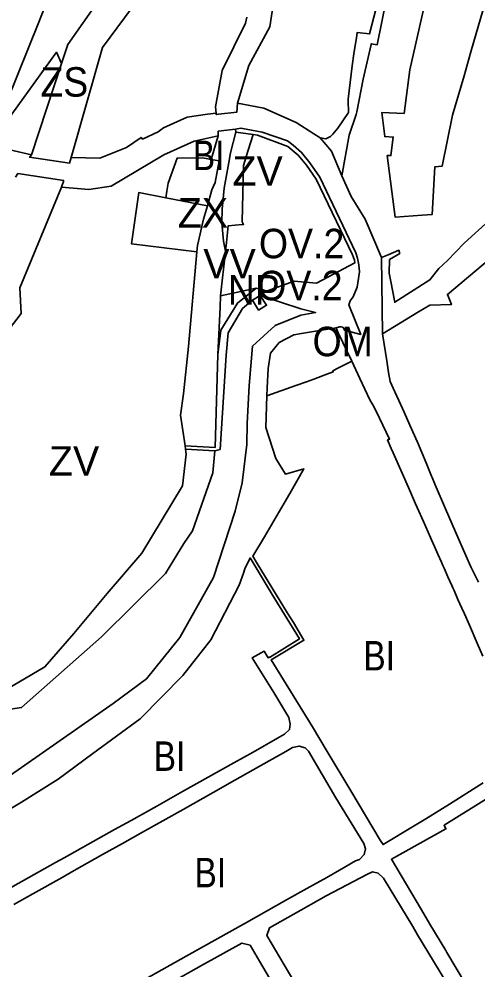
# Model space of a CAD drawing. Extents: x -650451 to -642268, y -1075216 to -1066610.
# Drawn here: x -646146.5 to -645913, y -1070420.9 to -1069937.3 of the extents above; entities that cross this region are included whole.
import ezdxf

# ---------------------------------------------------------------- set-up
doc = ezdxf.new("R2010")
doc.units = 0
doc.header["$LTSCALE"] = 6
doc.layers.add('1', color=7, linetype='Continuous', lineweight=35)
doc.layers.add('2', color=7, linetype='Continuous')

msp = doc.modelspace()

# ---------------------------------------------------------------- linework, layer by layer
at = {"layer": '1'}
for p, q in [((-646124.96, -1069959.99), (-646140.27, -1070006.41)), ((-646036.36, -1069993.34), (-646036.22, -1069994.85)), ((-646027.457, -1069996.063), (-646036.22, -1069994.85)), ((-646045.22, -1069996.81), (-646048.71, -1070008.77)), ((-646140.27, -1070006.41), (-646161.71, -1070001.55)), ((-646120.91, -1070010.7), (-646119.95, -1070007.73)), ((-646123.74, -1070019.41), (-646124.87, -1070022.9)), ((-646050.67, -1070032.37), (-646071.84, -1070028.3)), ((-646041.54, -1070055.39), (-646043.98, -1070078.24)), ((-645961.65, -1070097.54), (-645962.08, -1070058.72)), ((-646043.98, -1070078.24), (-646025.87, -1070074.25)), ((-646027.71, -1070080.48), (-646023.84, -1070078.03)), ((-646061.8, -1070156.29), (-646062.06, -1070154.56)), ((-646061.8, -1070156.29), (-646046.84, -1070157.03))]:
    msp.add_line(p, q, dxfattribs=at)
for points in [[(-645957.35, -1069496.35), (-645944.19, -1069571.66), (-645941.5, -1069609.76), (-645942.58, -1069624.73), (-645943.44, -1069636.76), (-645948.61, -1069657.43), (-645970.08, -1069692.61), (-646009.2, -1069734.98), (-646031.15, -1069747.2), (-646040.53, -1069755.58), (-646051.95, -1069771.98), (-646062.91, -1069794.85), (-646068.64, -1069840.94), (-646076.24, -1069876.52), (-646086.68, -1069900.4), (-646121.75, -1069950.24), (-646124.96, -1069959.99)], [(-645929.263, -1069881.347), (-645947.741, -1069963.127), (-645950.559, -1069985.34), (-645962, -1069984.94), (-645960.43, -1069997.16), (-645956.11, -1069997.41), (-645957.26, -1070006.85), (-645959.2, -1070006.76), (-645955.17, -1070038.09), (-645941.45, -1070037.17), (-645936.31, -1070036.82), (-645934.98, -1070012.58), (-645931.29, -1070012.23), (-645925.98, -1069986.2), (-645920.018, -1069966.193), (-645916.63, -1069954.05), (-645907.94, -1069924.17)], [(-646077.78, -1069916.11), (-646104.04, -1069951.75), (-646119.95, -1070007.73)], [(-646035.42, -1069980.12), (-646029.65, -1069960.92), (-646018.88, -1069941.32), (-646015.46, -1069918.63)], [(-646136.88, -1069923.39), (-646136.23, -1069923.94), (-646131.96, -1069927.57), (-646135.28, -1069935.88), (-646136.46, -1069938.84), (-646152.59, -1069978.9), (-646160.09, -1069997.51)], [(-645993.26, -1069997.71), (-645990.38, -1069998.22), (-645988.11, -1069997.06), (-645986.87, -1069995.99), (-645984.31, -1069992.78), (-645978.91, -1069984.88), (-645979.02, -1069978.79), (-645979.11, -1069978.07), (-645977.08, -1069961.2), (-645976.18, -1069954.95), (-645974.7, -1069945.76), (-645974.41, -1069944.11), (-645968.18, -1069944.85), (-645963.78, -1069927.8)], [(-645982.2, -1070017.17), (-645978.48, -1069996.42), (-645975, -1069985.96), (-645974.71, -1069984.49), (-645971.46, -1069967.93), (-645967.35, -1069950.26), (-645967.3, -1069949.88), (-645964.26, -1069950.41), (-645959.68, -1069927.82)], [(-646046.28, -1069985.18), (-646046.63, -1069982.04), (-646043.2, -1069963.46), (-646031.24, -1069939.45), (-646030.62, -1069936.3)], [(-645962.08, -1070058.72), (-645958.65, -1070057.27), (-645953.31, -1070055.02), (-645952.77, -1070056.63), (-645958.05, -1070059.79), (-645958.13, -1070066.59), (-645957.02, -1070072.53), (-645956.65, -1070074.52), (-645955.34, -1070081.48), (-645937.48, -1070070.14), (-645932.87, -1070064.33), (-645928.56, -1070060.21), (-645920.07, -1070051.36), (-645907.27, -1070039.82), (-645904.28, -1070034.66), (-645902.17, -1070025.11), (-645907.7, -1069998.79), (-645907.79, -1069986.84), (-645905.05, -1069967.45), (-645901.65, -1069959.39), (-645887.58, -1069932.97)], [(-646161.71, -1070001.55), (-646127.44, -1069954.2), (-646124.96, -1069959.99)], [(-646046.28, -1069985.18), (-646046.2, -1069985.92), (-646045.07, -1069985.73), (-646035.75, -1069984.73), (-646035.42, -1069980.12)], [(-645993.26, -1069997.71), (-645996.47, -1069995.79), (-646005.51, -1069989.96), (-646021.98, -1069982.59), (-646035.42, -1069980.12)], [(-646119.95, -1070007.73), (-646105.35, -1070008.18), (-646091.87, -1070002.66), (-646084.39, -1069997.53), (-646083.67, -1069998.4), (-646075.69, -1069994.68), (-646073.1, -1069992.61), (-646060.94, -1069987.19), (-646050.68, -1069985.78), (-646046.28, -1069985.18)], [(-646045.22, -1069996.81), (-646045.27, -1069994.44), (-646036.36, -1069993.34)], [(-646036.22, -1069994.85), (-646038.93, -1070005.37), (-646039.83, -1070010.38), (-646042.16, -1070023.43), (-646043.21, -1070034.06), (-646043.4, -1070040.96), (-646042.55, -1070050.3), (-646041.54, -1070055.39)], [(-645985.08, -1070094.46), (-645983.46, -1070094.05), (-645982.59, -1070093.99), (-645981.81, -1070094.21), (-645981.22, -1070094.8), (-645980.87, -1070095.64), (-645972.61, -1070097.85), (-645978.63, -1070082.76), (-645977.95, -1070080.77), (-645976.51, -1070078.72), (-645974.45, -1070073.8), (-645974.15, -1070071.55), (-645973.35, -1070065.91), (-645973.7, -1070062.5), (-645974.34, -1070059.01), (-645975.23, -1070056.35), (-645993.49, -1070017.76), (-645998.52, -1070010.49), (-646002.77, -1070005.2), (-646006.96, -1070001.52), (-646009.87, -1069999.35), (-646022.89, -1069994.84), (-646033.61, -1069992.78), (-646036.36, -1069993.34)], [(-646124.87, -1070022.9), (-646111.08, -1070024.01), (-646099.71, -1070022.3), (-646072.89, -1070006.37), (-646057.37, -1069999.5), (-646045.22, -1069996.81)], [(-646041.54, -1070055.39), (-646041.01, -1070051.13), (-646040.1, -1070042.52), (-646032.95, -1070041.88), (-646032.292, -1070041.824), (-646032.994, -1070040.508), (-646032.35, -1070011.78), (-646030.01, -1070004.12), (-646027.457, -1069996.063)], [(-646027.457, -1069996.063), (-646025.17, -1069996.38), (-646009.73, -1070002.19), (-646004.53, -1070006.52), (-646000.31, -1070011.7), (-645995.37, -1070018.86), (-645976.76, -1070057.39), (-645975.86, -1070060.04), (-645975.667, -1070061.487), (-645995.242, -1070071.816), (-646006.589, -1070070.734), (-646020.53, -1070075.79), (-646022.31, -1070075.07), (-646025.87, -1070074.25)], [(-645982.2, -1070017.17), (-645987.45, -1070004.6), (-645993.26, -1069997.71)], [(-646140.27, -1070006.41), (-646141.14, -1070007.63), (-646120.91, -1070010.7)], [(-646048.71, -1070008.77), (-646051.35, -1070008.32), (-646053.4, -1070007.98), (-646066.06, -1070008.11), (-646070.67, -1070020.78), (-646071.32, -1070024.95), (-646071.84, -1070028.3)], [(-646050.67, -1070032.37), (-646048.34, -1070024.27), (-646046.8, -1070020.55), (-646044.63, -1070009.47), (-646048.71, -1070008.77)], [(-646123.74, -1070019.41), (-646147.11, -1070016.01), (-646148.34, -1070017.73)], [(-645982.2, -1070017.17), (-645977.5, -1070027.72), (-645970.39, -1070039.12), (-645962.08, -1070058.72)], [(-646160.94, -1070129.14), (-646160.6, -1070127.76), (-646151.53, -1070095.19), (-646145.47, -1070087.27), (-646146.19, -1070074.15), (-646124.87, -1070022.9)], [(-646071.84, -1070028.3), (-646085.64, -1070025.65), (-646089.25, -1070051.8), (-646056.09, -1070055.76)], [(-646056.09, -1070055.76), (-646055.78, -1070052.52), (-646052.63, -1070039.21), (-646050.67, -1070032.37)], [(-646056.09, -1070055.76), (-646060.36, -1070103.99), (-646062.8, -1070128.04), (-646064.44, -1070138.99), (-646062.06, -1070154.56)], [(-645901.22, -1070066.97), (-645907.18, -1070059.55), (-645928.51, -1070077.51), (-645926.55, -1070082.68), (-645937.53, -1070082.92), (-645943.32, -1070086.36), (-645961.65, -1070097.54)], [(-646025.87, -1070074.25), (-646035.35, -1070081.89), (-646043.88, -1070095.63), (-646045.35, -1070108.04)], [(-646023.84, -1070078.03), (-646003.18, -1070084.88), (-645995.59, -1070086.74), (-646003.08, -1070088.07), (-646016.12, -1070093.28), (-646027.66, -1070103.79), (-646029.45, -1070123.88), (-646030.51, -1070143.17), (-646030.66, -1070153.86), (-646033.06, -1070173.32), (-646036.61, -1070187.84), (-646047.55, -1070221.59), (-646064.78, -1070252.22), (-646081.74, -1070273.1), (-646098.57, -1070285.71), (-646152.57, -1070323.39), (-646159.26, -1070328.75)], [(-646046.84, -1070157.03), (-646044.21, -1070156.41), (-646041.14, -1070108.39), (-646040.05, -1070097.06), (-646032.79, -1070084.73), (-646027.71, -1070080.48)], [(-646043.98, -1070078.24), (-646044.25, -1070084.03), (-646045.35, -1070108.04)], [(-646023.84, -1070078.03), (-646020.6, -1070082.99), (-646024.66, -1070085.49), (-646027.71, -1070080.48)], [(-646020.39, -1070129.18), (-646020.23, -1070125.05), (-646019.71, -1070115.15), (-646018.64, -1070107.32), (-646014.13, -1070101.92), (-646006.74, -1070098.07), (-646002.8, -1070097.37), (-645992.6, -1070095.69), (-645985.08, -1070094.46)], [(-645985.08, -1070094.46), (-645984.1, -1070097.01), (-645977.22, -1070111.51)], [(-645961.65, -1070097.54), (-645959.4, -1070111.28), (-645958.45, -1070117.18), (-645957.7, -1070121.77), (-645955.23, -1070127.14), (-645955.07, -1070127.5), (-645950.6, -1070137.43), (-645947.63, -1070144.02), (-645943.7, -1070152.62), (-645939.36, -1070163.29), (-645936.57, -1070170.09), (-645936.3, -1070170.74), (-645934.81, -1070174.36), (-645929.6, -1070186.7), (-645924.42, -1070198.42), (-645919.15, -1070210.32), (-645916.58, -1070216.14), (-645912.71, -1070223.91)], [(-646045.35, -1070108.04), (-646046.76, -1070155.43), (-646062.06, -1070154.56)], [(-645977.22, -1070111.51), (-645983.92, -1070114.9), (-645986.83, -1070116.33), (-645986.61, -1070116.88), (-645989.89, -1070118.09), (-645996.56, -1070120.56), (-646000.31, -1070121.94), (-646005.76, -1070123.86), (-646020.39, -1070129.18)], [(-645910.44, -1070261.69), (-645913.34, -1070255.1), (-645917.38, -1070245.91), (-645919.93, -1070240.15), (-645921.25, -1070237.16), (-645923.2, -1070232.72), (-645925.17, -1070228.27), (-645925.76, -1070226.93), (-645926.31, -1070225.7), (-645928.27, -1070221.25), (-645930.23, -1070216.81), (-645930.8, -1070215.5), (-645931.55, -1070213.82), (-645933.34, -1070209.76), (-645935.11, -1070205.74), (-645936.58, -1070202.44), (-645937.14, -1070201.19), (-645940.68, -1070193.11), (-645943.86, -1070186.04), (-645944.71, -1070184.17), (-645948.35, -1070175.83), (-645951.58, -1070168.55), (-645956.17, -1070158.1), (-645957.09, -1070155.97), (-645958.99, -1070151.56), (-645957.96, -1070151.1), (-645961.36, -1070144), (-645964.79, -1070136.9), (-645966.53, -1070133.78), (-645968.02, -1070131.18), (-645973.11, -1070120.3), (-645977.22, -1070111.51)], [(-645910.33, -1070326.19), (-645927.52, -1070336.95), (-645939.51, -1070344.47), (-645945.44, -1070348.04), (-645961.29, -1070357.59), (-645962.69, -1070355.25), (-645977.73, -1070330.16), (-645989.72, -1070310.12), (-645997.17, -1070297.57), (-646011.89, -1070273.62), (-646018.27, -1070263.54), (-646001.55, -1070253.52), (-646006.95, -1070244.46), (-646009.96, -1070239.67), (-646025.32, -1070214.44), (-646027.5, -1070210.78), (-646021.68, -1070200.97), (-646015.63, -1070190.78), (-646008.75, -1070178.83), (-646001.55, -1070166.34), (-646010.94, -1070168.93), (-646015.86, -1070161.08), (-646021, -1070145.27), (-646020.39, -1070129.18)], [(-646046.84, -1070157.03), (-646047.97, -1070168.31), (-646058.29, -1070197.88), (-646062.69, -1070204.21), (-646072.06, -1070219.56), (-646104.49, -1070251.8), (-646145.19, -1070287.85), (-646168.86, -1070291.34), (-646203.06, -1070281.27), (-646228.96, -1070273.65), (-646235.69, -1070273.19), (-646240.68, -1070272.84), (-646265.2, -1070280.49), (-646302.98, -1070303.43), (-646313.77, -1070309.99), (-646359.41, -1070334.2), (-646391.97, -1070362.11), (-646415.34, -1070392.15), (-646478.77, -1070449), (-646505.87, -1070462.81), (-646524.86, -1070460.39), (-646575.64, -1070436.46), (-646588.54, -1070434.24), (-646599.32, -1070439.31)], [(-646210.38, -1070267.68), (-646206.77, -1070269.12), (-646174.12, -1070280.47), (-646156.17, -1070280.5), (-646133.33, -1070267.1), (-646118.58, -1070250.17), (-646101.61, -1070229.78), (-646084.06, -1070209.26), (-646063.42, -1070175.01), (-646061.41, -1070158.85), (-646061.8, -1070156.29)], [(-646167.27, -1070349.09), (-646145.23, -1070336), (-646126.59, -1070324.33), (-646108.9, -1070311.25), (-646084.97, -1070293.57), (-646063.14, -1070271.56), (-646048.94, -1070253.4), (-646034.53, -1070225.58), (-646032.36, -1070219.45), (-646031.59, -1070217.26), (-646029, -1070211.63), (-646017.67, -1070230.24), (-646003.89, -1070252.88), (-646019.06, -1070262.29), (-646019.19, -1070262.09), (-646019.81, -1070262.45), (-646021.85, -1070259.08), (-646027.85, -1070262.42), (-646016.79, -1070280.17), (-646009.17, -1070292.79), (-646008.5, -1070296.25), (-646008.91, -1070299.03), (-646011.51, -1070301.37), (-646014.98, -1070303.38), (-646027.47, -1070310.49), (-646037.19, -1070315.94), (-646063.37, -1070330.6), (-646076.45, -1070337.93), (-646089.54, -1070345.26), (-646097.91, -1070349.95), (-646108.74, -1070356.01), (-646123.57, -1070364.32), (-646127.93, -1070366.76), (-646170.01, -1070390.33)], [(-646149.2, -1070388.06), (-646139.51, -1070382.62), (-646124.65, -1070374.27), (-646118.41, -1070370.76), (-646103.98, -1070362.66), (-646093.88, -1070356.98), (-646083.62, -1070351.23), (-646073.33, -1070345.44), (-646063.09, -1070339.69), (-646042.72, -1070328.18), (-646039.46, -1070326.33), (-646021.94, -1070316.43), (-646010.74, -1070310.17), (-646007.34, -1070308.14), (-646004.04, -1070307.45), (-646000.86, -1070308.34), (-645999.24, -1070309.95), (-645985.26, -1070333.71), (-645971.03, -1070356.94), (-645970.25, -1070359.71), (-645970.88, -1070362.62), (-645973.25, -1070365.19), (-645975.27, -1070365.89), (-645980.32, -1070368.8), (-645989.89, -1070374.31), (-646000.1, -1070379.99), (-646010.35, -1070385.73), (-646030.8, -1070397.2), (-646061.44, -1070414.39), (-646081.95, -1070425.89)], [(-645914.16, -1070437.25), (-645928.8, -1070412.52), (-645929.43, -1070411.46), (-645937.48, -1070398), (-645941.77, -1070390.84), (-645949.43, -1070377.9), (-645957.06, -1070365.02), (-645929.29, -1070349.59), (-645930.25, -1070347.73), (-645906.49, -1070332.99), (-645904.62, -1070331.84), (-645894.57, -1070325.46), (-645889.89, -1070321.24), (-645888.43, -1070322.74), (-645884.88, -1070319.37)], [(-645886.41, -1070498.83), (-645887.31, -1070497.33), (-645897.23, -1070480.83), (-645900.37, -1070475.61), (-645909.07, -1070461.12), (-645921.5, -1070440.43), (-645930.78, -1070425), (-645932.75, -1070421.72), (-645943.71, -1070403.5), (-645946.22, -1070399.32), (-645961.01, -1070374.71), (-645963.76, -1070372.18), (-645966.73, -1070371.37), (-645969.23, -1070372.54), (-645990.19, -1070383.7), (-646007.11, -1070393.19), (-646019.14, -1070399.94), (-646020.36, -1070403.89), (-646009.33, -1070422.47), (-645997, -1070443.23), (-645985.06, -1070463.18), (-645974.83, -1070480.36), (-645953.43, -1070516.32), (-645941.2, -1070537.55)], [(-646017.38, -1070428.4), (-646024.17, -1070416.95), (-646029, -1070408.81), (-646033.15, -1070407.7), (-646053.6, -1070419.15), (-646089.82, -1070439.46)]]:
    msp.add_lwpolyline(points, dxfattribs=at)

# ---------------------------------------------------------------- texts
at = {"layer": '2'}
for s, width, p in [('ZS', 0.95, (-646135.67, -1069976.81)), ('BI', 0.85, (-646058.13, -1070014.223)), ('OV.2', 0.95, (-646024.46, -1070059.07)), ('NP', 0.95, (-646040.299, -1070082.639)), ('OV.2', 0.95, (-646025.32, -1070080.45)), ('OM', 0.95, (-645997.17, -1070108.95)), ('BI', 0.85, (-645971.328, -1070268.929)), ('BI', 0.85, (-646078.014, -1070320.049)), ('BI', 0.85, (-646057.27, -1070379.319))]:
    msp.add_text(s, height=15, dxfattribs=dict(at, width=width)).set_placement(p)
for s, p in [('ZV', (-646037.94, -1070022.11)), ('ZX', (-646065.79, -1070043.479)), ('VV', (-646052.777, -1070069.284)), ('ZV', (-646131.34, -1070169.758))]:
    msp.add_text(s, height=15, dxfattribs=at).set_placement(p)

doc.saveas('drawing.dxf')
